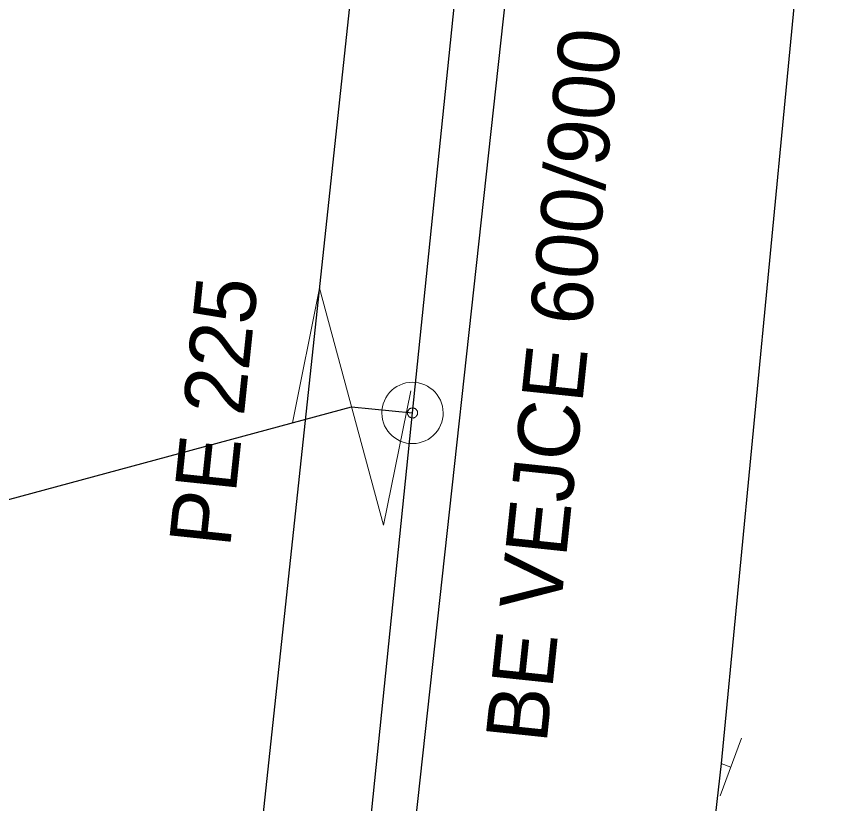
# Model space of a CAD drawing. Extents: x -783064 to -782702, y -1007904 to -1007145.
# Drawn here: x -782810.93 to -782797.57, y -1007614.35 to -1007601.52 of the extents above; entities that cross this region are included whole.
import ezdxf

# ---------------------------------------------------------------- set-up
doc = ezdxf.new("R2010")
doc.units = 0
doc.header["$LTSCALE"] = 0.4
for name, color, linetype, lineweight in [('1', 7, 'Continuous', 13), ('14', 7, 'Continuous', 13), ('17', 7, 'Continuous', 25), ('31', 7, 'Continuous', 13), ('34', 7, 'Continuous', 13)]:
    doc.layers.add(name, color=color, linetype=linetype, lineweight=lineweight)

msp = doc.modelspace()

# ---------------------------------------------------------------- linework, layer by layer
at = {"layer": '14', "lineweight": 25}
for p, q in [((-782807.829, -1007645.75), (-782798.949, -1007564.67)), ((-782826.278, -1007613.498), (-782805.465, -1007607.877)), ((-782805.465, -1007607.877), (-782804.471, -1007607.979)), ((-782805.25, -1007615.57), (-782804.471, -1007607.979))]:
    msp.add_line(p, q, dxfattribs=at)
at = {"layer": '14'}
msp.add_line((-782799.44, -1007613.69), (-782799.28, -1007613.75), dxfattribs=at)
at = {"layer": '14', "lineweight": 25}
msp.add_lwpolyline([(-782804.471, -1007607.979), (-782803.131, -1007594.908), (-782802.837, -1007592.043), (-782801.112, -1007575.211), (-782800.399, -1007568.31)], dxfattribs=at)
at = {"layer": '17'}
for points in [[(-782801.55, -1007565.42), (-782803.719, -1007584.76), (-782806.96, -1007615), (-782809.59, -1007640.17), (-782810.57, -1007649.22)], [(-782797.572, -1007594.291), (-782799.44, -1007613.69), (-782801.199, -1007629.14), (-782801.87, -1007634.05), (-782802.967, -1007644.343), (-782805.123, -1007667.966)]]:
    msp.add_lwpolyline(points, dxfattribs=at)
at = {"layer": '31'}
msp.add_lwpolyline([(-782806.43, -1007608.138), (-782805.986, -1007605.946), (-782804.943, -1007609.808), (-782804.499, -1007607.616)], dxfattribs=at)
for points in [[(-782803.982, -1007607.87), (-782803.997, -1007607.82), (-782804.016, -1007607.771), (-782804.04, -1007607.725), (-782804.068, -1007607.681), (-782804.102, -1007607.641), (-782804.14, -1007607.604), (-782804.181, -1007607.572), (-782804.225, -1007607.544), (-782804.271, -1007607.52), (-782804.32, -1007607.502), (-782804.371, -1007607.488), (-782804.423, -1007607.481), (-782804.475, -1007607.479), (-782804.527, -1007607.482), (-782804.579, -1007607.49), (-782804.629, -1007607.505), (-782804.678, -1007607.524), (-782804.725, -1007607.548), (-782804.768, -1007607.576), (-782804.808, -1007607.61), (-782804.845, -1007607.648), (-782804.878, -1007607.689), (-782804.906, -1007607.733), (-782804.93, -1007607.779), (-782804.947, -1007607.828), (-782804.961, -1007607.879), (-782804.969, -1007607.931), (-782804.97, -1007607.983), (-782804.967, -1007608.035), (-782804.959, -1007608.087), (-782804.944, -1007608.137), (-782804.925, -1007608.186), (-782804.902, -1007608.233), (-782804.873, -1007608.276), (-782804.839, -1007608.316), (-782804.802, -1007608.353), (-782804.761, -1007608.386), (-782804.717, -1007608.414), (-782804.67, -1007608.438), (-782804.621, -1007608.455), (-782804.57, -1007608.469), (-782804.519, -1007608.477), (-782804.466, -1007608.478), (-782804.414, -1007608.475), (-782804.362, -1007608.467), (-782804.312, -1007608.452), (-782804.263, -1007608.433), (-782804.217, -1007608.41), (-782804.173, -1007608.381), (-782804.133, -1007608.347), (-782804.096, -1007608.31), (-782804.064, -1007608.269), (-782804.036, -1007608.225), (-782804.012, -1007608.178), (-782803.994, -1007608.129), (-782803.98, -1007608.078), (-782803.973, -1007608.027), (-782803.971, -1007607.974), (-782803.974, -1007607.922)], [(-782804.39, -1007607.961), (-782804.392, -1007607.952), (-782804.396, -1007607.945), (-782804.4, -1007607.937), (-782804.404, -1007607.93), (-782804.41, -1007607.923), (-782804.416, -1007607.917), (-782804.423, -1007607.912), (-782804.43, -1007607.907), (-782804.438, -1007607.904), (-782804.446, -1007607.9), (-782804.455, -1007607.898), (-782804.463, -1007607.897), (-782804.471, -1007607.897), (-782804.479, -1007607.896), (-782804.488, -1007607.898), (-782804.497, -1007607.9), (-782804.504, -1007607.904), (-782804.512, -1007607.908), (-782804.519, -1007607.912), (-782804.526, -1007607.918), (-782804.532, -1007607.924), (-782804.537, -1007607.931), (-782804.542, -1007607.938), (-782804.546, -1007607.946), (-782804.549, -1007607.954), (-782804.551, -1007607.963), (-782804.552, -1007607.971), (-782804.552, -1007607.979), (-782804.553, -1007607.987), (-782804.551, -1007607.996), (-782804.549, -1007608.005), (-782804.545, -1007608.012), (-782804.541, -1007608.02), (-782804.537, -1007608.027), (-782804.531, -1007608.034), (-782804.526, -1007608.04), (-782804.518, -1007608.045), (-782804.511, -1007608.05), (-782804.503, -1007608.054), (-782804.495, -1007608.057), (-782804.486, -1007608.059), (-782804.478, -1007608.06), (-782804.47, -1007608.06), (-782804.462, -1007608.061), (-782804.453, -1007608.059), (-782804.444, -1007608.057), (-782804.437, -1007608.053), (-782804.429, -1007608.049), (-782804.422, -1007608.045), (-782804.415, -1007608.039), (-782804.409, -1007608.034), (-782804.404, -1007608.026), (-782804.399, -1007608.019), (-782804.396, -1007608.011), (-782804.392, -1007608.003), (-782804.39, -1007607.994), (-782804.389, -1007607.986), (-782804.389, -1007607.978), (-782804.388, -1007607.97)]]:
    msp.add_lwpolyline(points, close=True, dxfattribs=at)
at = {"layer": '34'}
msp.add_line((-782799.104, -1007613.281), (-782799.456, -1007614.217), dxfattribs=at)

# ---------------------------------------------------------------- texts
at = {"layer": '1'}
for s, p in [('BE VEJCE 600/900', (-782802.286, -1007613.377)), ('PE 225', (-782807.447, -1007610.187))]:
    msp.add_text(s, height=1, rotation=84, dxfattribs=at).set_placement(p)

doc.saveas('drawing.dxf')
